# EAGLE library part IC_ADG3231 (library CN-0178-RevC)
1.65V to 3.6V single channel, bi-directional level translator with uni-directional signal path.
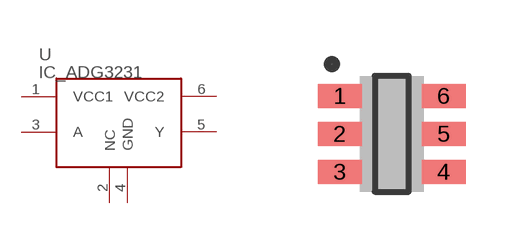
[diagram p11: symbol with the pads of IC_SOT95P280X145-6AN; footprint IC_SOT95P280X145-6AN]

Designator prefix -

## IC_ADG3231_SOT-23  [IC_SOT95P280X145-6AN]
1  VCC1
2  NC
3  A
4  GND
5  Y
6  VCC2

## Footprint IC_SOT95P280X145-6AN (pad centres in mm)
(SOT-23-6), 0.95mm, pitch; 6 pin, 1.60mm W x 2.90mm L x 1.45mm H Body
smd 1.1 x 0.6: 1 -1.3,0.95; 2 -1.3,0; 3 -1.3,-0.95; 4 1.3,-0.95; 5 1.3,0; 6 1.3,0.95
